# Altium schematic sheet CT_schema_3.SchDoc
size 293 x 156 mm
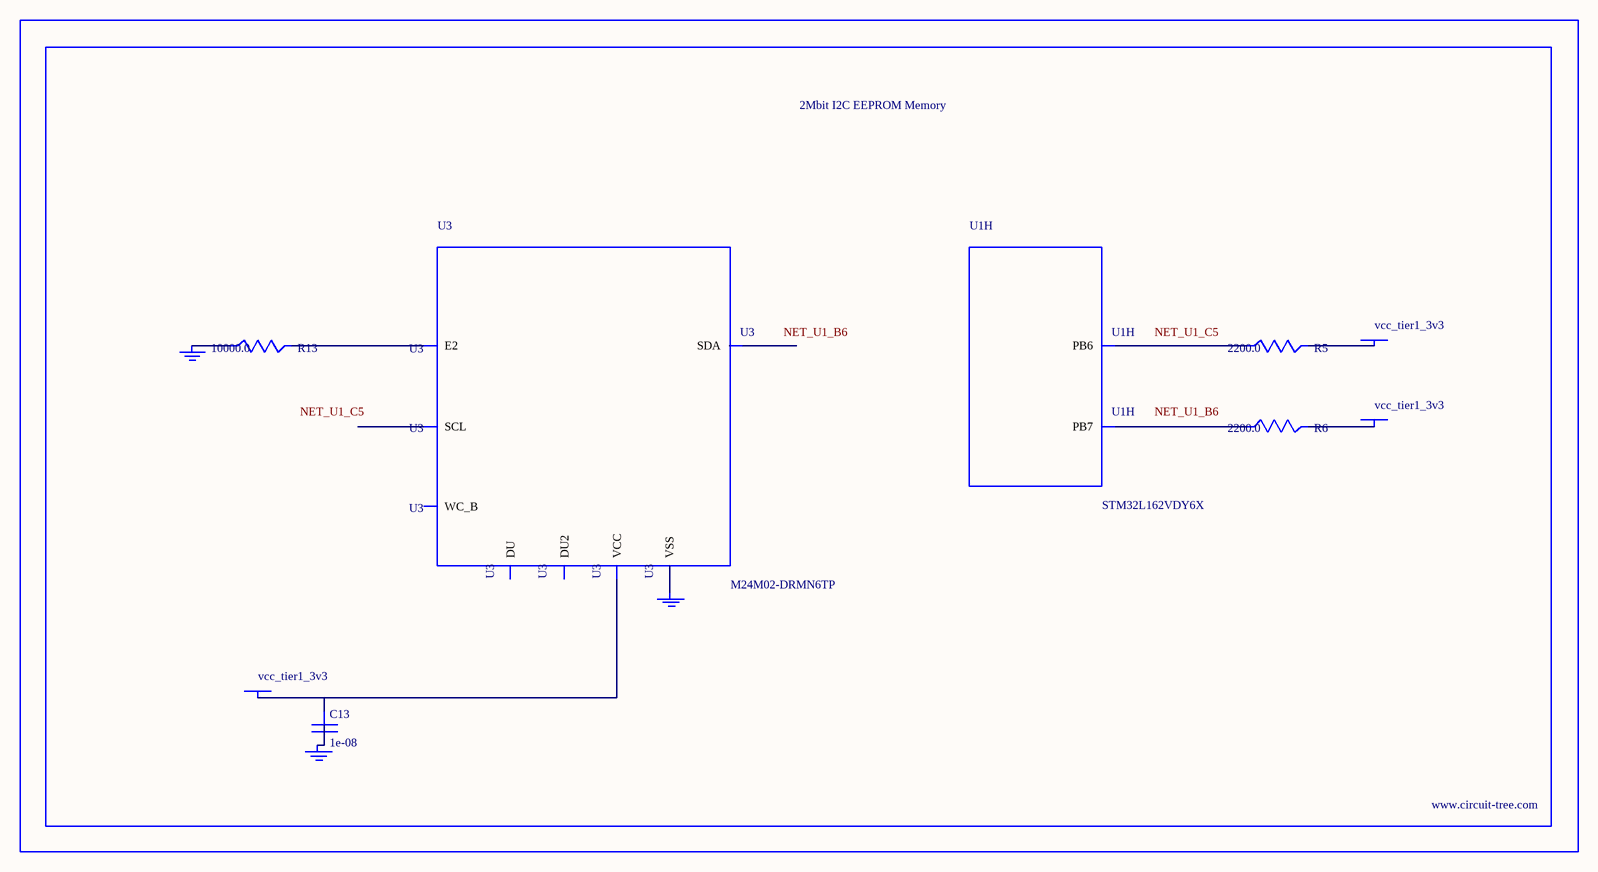
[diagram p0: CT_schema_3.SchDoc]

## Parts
BORDER2  (no value)
C13  1e-08  [C0402]
GND_INSTANCE_2_0  (no value)
GND_INSTANCE_2_1  (no value)
GND_INSTANCE_2_2  (no value)
POWER_INSTANCE_2_0  vcc_tier1_3v3
POWER_INSTANCE_2_1  vcc_tier1_3v3
POWER_INSTANCE_2_2  vcc_tier1_3v3
R5  2200.0  [R0603]
R6  2200.0  [R0603]
R13  10000.0  [R0603]
U1  STM32L162VDY6X  [WLCSP104]  (part H of 9)
U3  M24M02-DRMN6TP  [SOIC-8]

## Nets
NetC13_1: C13.1 POWER_INSTANCE_2_0.0(PWR) U3.8(VCC)
NetC13_2: C13.2 GND_INSTANCE_2_1.0(GND)
NetGND_INSTANCE_2_0_0: GND_INSTANCE_2_0.0(GND) R13.1
NetGND_INSTANCE_2_2_0: GND_INSTANCE_2_2.0(GND) U3.4(VSS)
NetPOWER_INSTANCE_2_1_0: POWER_INSTANCE_2_1.0(PWR) R5.2
NetPOWER_INSTANCE_2_2_0: POWER_INSTANCE_2_2.0(PWR) R6.2
NetR5_1: R5.1 U1.C5(PB6)
NetR6_1: R6.1 U1.B6(PB7)
NetR13_2: R13.2 U3.3(E2)

Not connected (* = marked no-connect by the designer): U3 1(DU) 2(DU2) 5(SDA) 6(SCL) 7(WC_B)

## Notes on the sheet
- Labels drawn without touching a wire or pin: NET_U1_B6, NET_U1_C5

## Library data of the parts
BORDER2 = BORDER_PAGE2
C13 = C0402C103K3RAC
GND_INSTANCE_2_0-GND_INSTANCE_2_2 = GND
POWER_INSTANCE_2_0-POWER_INSTANCE_2_2 = PWR
R5 R6 = RC0603JR-072K2L
R13 = RC0603JR-0710KL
